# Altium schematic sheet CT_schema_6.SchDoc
size 274 x 160 mm
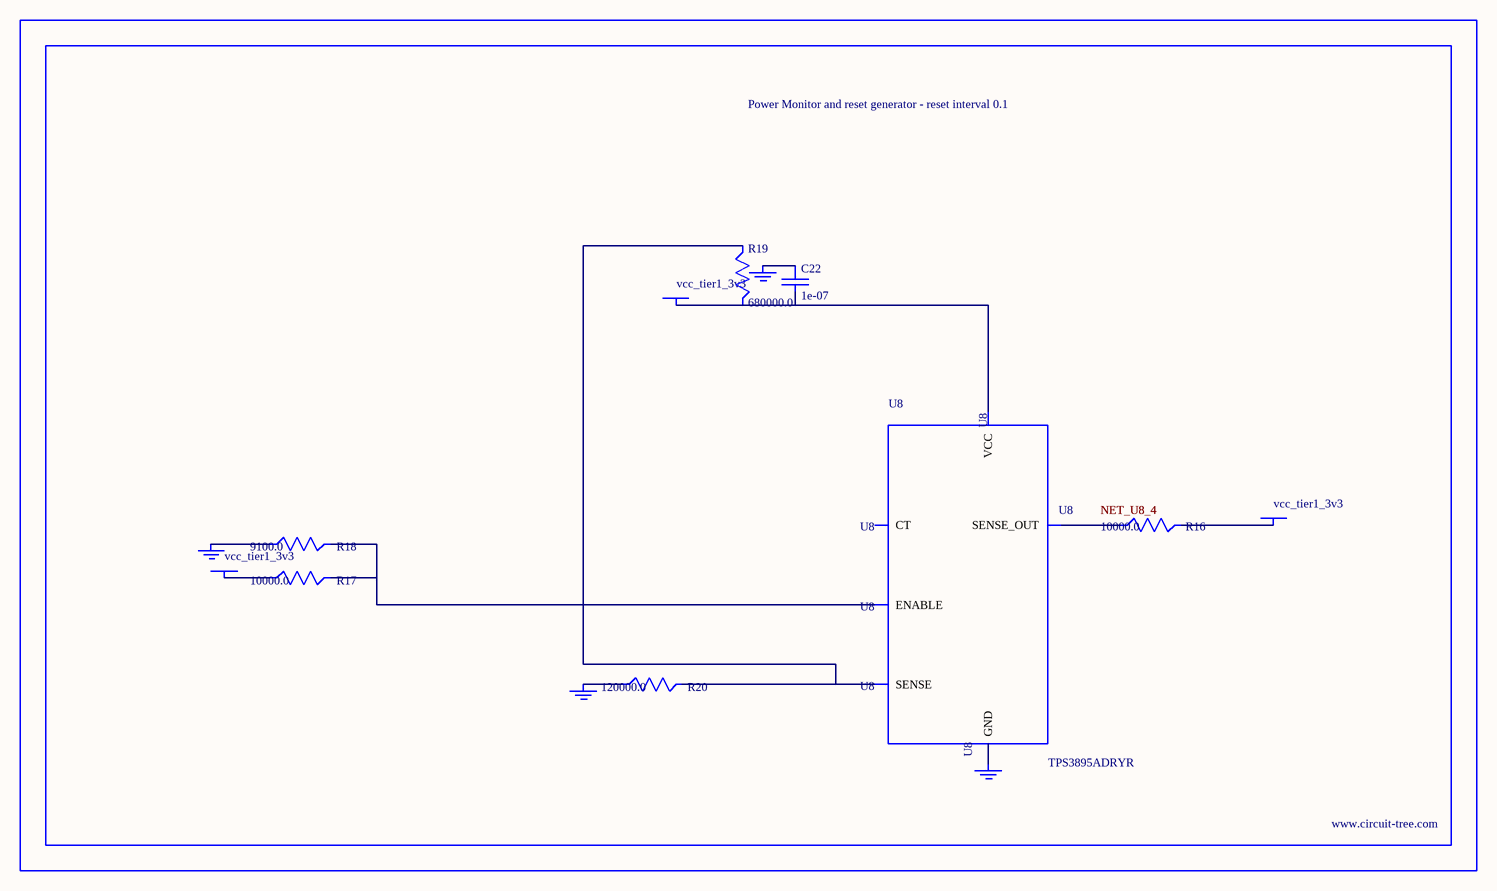
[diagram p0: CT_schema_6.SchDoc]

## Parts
BORDER5  (no value)
C22  1e-07  [C0402]
GND_INSTANCE_5_0  (no value)
GND_INSTANCE_5_1  (no value)
GND_INSTANCE_5_2  (no value)
GND_INSTANCE_5_3  (no value)
POWER_INSTANCE_5_0  vcc_tier1_3v3
POWER_INSTANCE_5_1  vcc_tier1_3v3
POWER_INSTANCE_5_2  vcc_tier1_3v3
R16  10000.0  [R0603]
R17  10000.0  [R0603]
R18  9100.0  [R0603]
R19  680000.0  [R0603]
R20  120000.0  [R0603]
U8  TPS3895ADRYR  [SON-6]

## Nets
NetC22_1: C22.1 GND_INSTANCE_5_2.0(GND)
NetC22_2: C22.2 POWER_INSTANCE_5_2.0(PWR) R19.2 U8.6(VCC)
NetGND_INSTANCE_5_0_0: GND_INSTANCE_5_0.0(GND) R18.1
NetGND_INSTANCE_5_1_0: GND_INSTANCE_5_1.0(GND) R20.1
NetGND_INSTANCE_5_3_0: GND_INSTANCE_5_3.0(GND) U8.2(GND)
NetPOWER_INSTANCE_5_0_0: POWER_INSTANCE_5_0.0(PWR) R17.1
NetPOWER_INSTANCE_5_1_0: POWER_INSTANCE_5_1.0(PWR) R16.2
NetR16_1: R16.1 U8.4(SENSE_OUT)
NetR17_2: R17.2 R18.2 U8.1(ENABLE)
NetR19_1: R19.1 R20.2 U8.3(SENSE)

Not connected (* = marked no-connect by the designer): U8 5(CT)

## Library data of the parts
BORDER5 = BORDER_PAGE5
C22 = C0402C104K3RACTU
GND_INSTANCE_5_0-GND_INSTANCE_5_3 = GND
POWER_INSTANCE_5_0-POWER_INSTANCE_5_2 = PWR
R16 R17 = RC0603JR-0710KL
R18 = RC0603JR-079K1L
R19 = RC0603JR-07680KL
R20 = RC0603JR-07120KL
